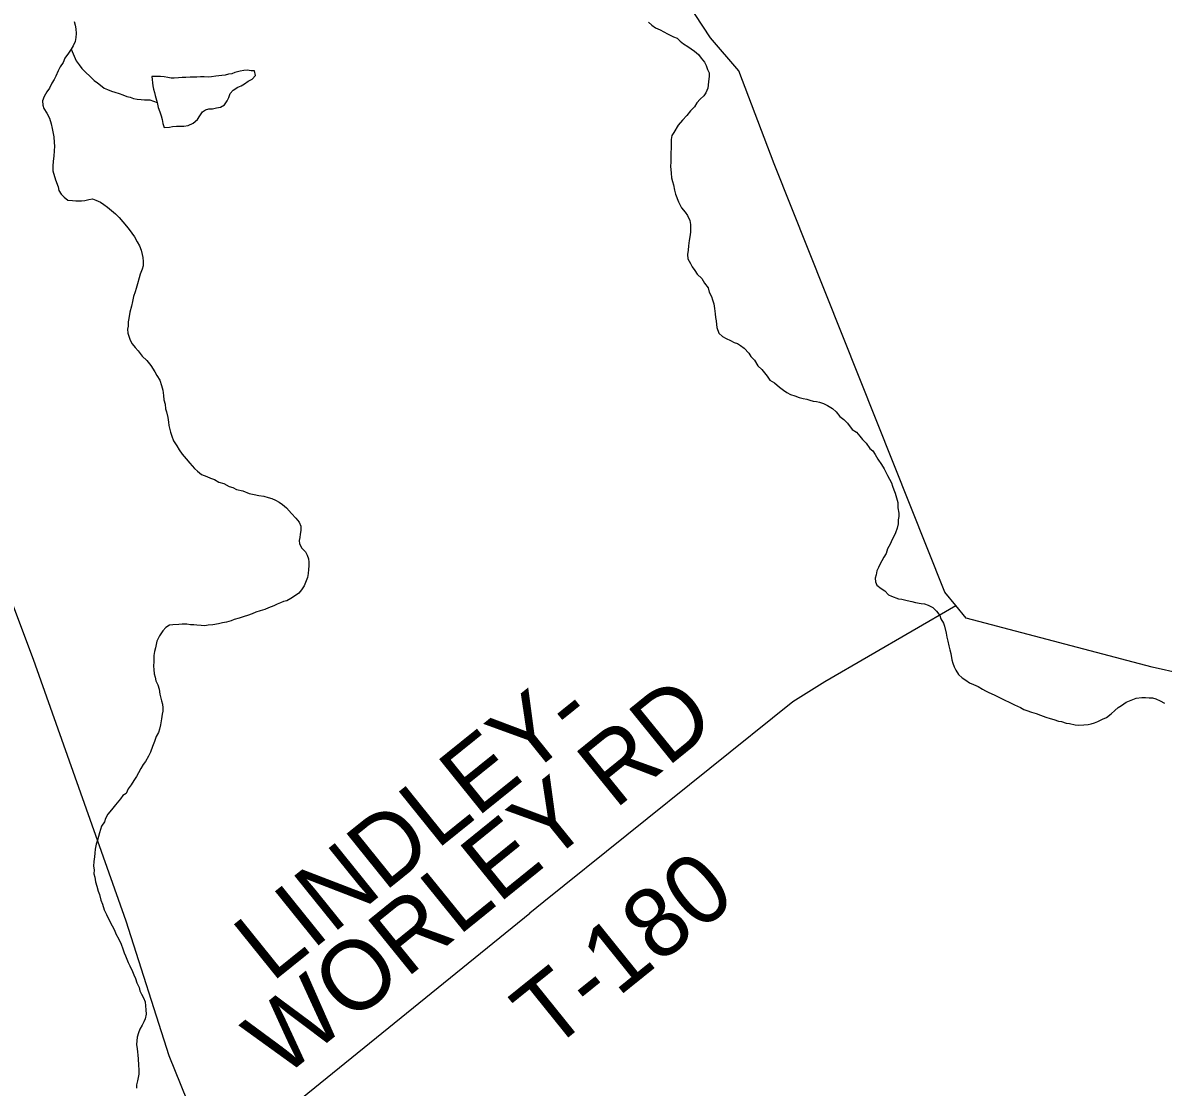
# Model space of a CAD drawing. Extents: x 1310247 to 1664935, y 284496 to 704931.
# Drawn here: x 1517006 to 1521928, y 471214 to 475811 of the extents above; entities that cross this region are included whole.
import ezdxf

# ---------------------------------------------------------------- set-up
doc = ezdxf.new("R2010")
doc.units = 0
for name, color, linetype in [('GM_X_County_Road_Text', 7, 'Continuous'), ('GM_X_County_Subdivision_Text', 7, 'Continuous'), ('GM_X_Minor_River', 7, 'Continuous'), ('GM_X_Minor_River_Text', 7, 'Continuous'), ('GM_X_Township_Subdivision', 7, 'Continuous')]:
    doc.layers.add(name, color=color, linetype=linetype)

msp = doc.modelspace()

# ---------------------------------------------------------------- linework, layer by layer
at = {"layer": 'GM_X_County_Road_Text'}
for points in [[(1512412.2, 479868.3), (1512884, 479728.6), (1513011.2, 479638.4), (1513334, 479148.4), (1513670.6, 478637.4), (1514118, 477962.6), (1514571.2, 477265.7), (1514855.2, 476804), (1515883.3, 475188.3), (1516518, 474094.8), (1516870.8, 473537.8), (1517050.2, 473063.7), (1517450.2, 471932.4), (1517635.9, 471351.9), (1517767.3, 471027)], [(1522264.5, 472942.8), (1521880.2, 473029), (1521078.1, 473239.9), (1521032.3, 473295.2), (1520985.4, 473351.7), (1520249.2, 475202.2), (1520096.8, 475603.6), (1519974.5, 475745.9), (1519874.5, 475897.9), (1519727.2, 476499.8), (1519621.9, 476700), (1519462.1, 476887), (1518873.3, 477511.8), (1518828.8, 477618.8), (1518824.3, 477628.5), (1518823.6, 477630)]]:
    msp.add_lwpolyline(points, dxfattribs=at)
at = {"layer": 'GM_X_County_Subdivision_Text'}
for points in [[(1519194.1, 471967.2), (1519255.2, 472016.7), (1520329.3, 472880.5), (1520467.2, 472966.6), (1521032.3, 473295.2)], [(1517839.6, 470867.7), (1519193.6, 471966.8), (1519194.1, 471967.2)]]:
    msp.add_lwpolyline(points, dxfattribs=at)
at = {"layer": 'GM_X_Minor_River'}
for points in [[(1517585.9, 475467.4), (1517590.2, 475445.6), (1517597.7, 475427.4), (1517603.3, 475409.2), (1517606.9, 475393.1), (1517610.5, 475376.9), (1517616.1, 475358.7), (1517638.2, 475360.2), (1517652.4, 475363.9), (1517668.5, 475365.5), (1517686.6, 475365.1), (1517700.6, 475364.7), (1517718.8, 475368.3), (1517741.1, 475377.8), (1517759.6, 475393.4), (1517770, 475409.2), (1517780.5, 475427), (1517794.8, 475434.7), (1517809, 475440.4), (1517825.1, 475440), (1517841.2, 475443.6), (1517859.4, 475447.2), (1517875.7, 475456.8), (1517888.2, 475474.6), (1517894.6, 475488.5), (1517901, 475506.4), (1517913.4, 475520.1), (1517933.9, 475533.7), (1517948.1, 475539.3), (1517962.3, 475547), (1517978.7, 475558.7), (1517995, 475568.3), (1518009.4, 475584), (1518005.9, 475604.2), (1517991.9, 475604.5), (1517973.8, 475607), (1517959.8, 475605.3), (1517943.6, 475601.7), (1517921.4, 475596.2), (1517907.2, 475590.5), (1517893, 475588.8), (1517878.9, 475585.2), (1517864.8, 475583.5), (1517838.6, 475580.1), (1517820.5, 475578.5), (1517806.4, 475576.9), (1517788.3, 475577.3), (1517772.2, 475577.7), (1517756.1, 475576.1), (1517742.1, 475576.4), (1517728, 475576.8), (1517709.9, 475575.2), (1517693.8, 475575.6), (1517677.7, 475574), (1517659.6, 475572.4), (1517645.6, 475572.7), (1517631.6, 475575.1), (1517615.5, 475577.5), (1517599.5, 475579.8), (1517562.9, 475578.7)], [(1517562.9, 475578.7), (1517566.4, 475538.5), (1517570, 475524.4), (1517573.7, 475510.2), (1517577.1, 475497)], [(1517577.1, 475497), (1517585.9, 475467.4)]]:
    msp.add_lwpolyline(points, dxfattribs=at)
at = {"layer": 'GM_X_Minor_River_Text'}
for points in [[(1517227.8, 475817.5), (1517231.4, 475801.4), (1517235, 475785.3), (1517236.5, 475765.2), (1517234.1, 475747.2), (1517231.7, 475731.2), (1517223.1, 475711.3), (1517214.8, 475697.5), (1517202.3, 475679.7), (1517187.7, 475658), (1517179.2, 475640.1), (1517166.6, 475620.4), (1517158.2, 475604.5), (1517147.6, 475580.7), (1517141.2, 475566.8)], [(1519706.6, 475814), (1519720.4, 475801.6), (1519736.1, 475789.2), (1519756, 475780.7), (1519771.9, 475772.3), (1519787.7, 475763.9), (1519813.5, 475751.2), (1519829.4, 475744.8), (1519843.2, 475732.5), (1519856.9, 475720.1), (1519876.8, 475709.6), (1519890.6, 475699.2), (1519904.4, 475688.8), (1519922.1, 475674.4), (1519933.7, 475658), (1519947.4, 475641.7), (1519955.1, 475627.4), (1519960.6, 475609.2), (1519968.3, 475595), (1519968, 475581), (1519965.4, 475557), (1519962.7, 475528.9), (1519954.1, 475509.1), (1519945.7, 475495.2), (1519929.3, 475481.6), (1519914.9, 475465.9), (1519904.4, 475448.1), (1519887.9, 475430.4), (1519871.3, 475410.7), (1519852.7, 475391.1), (1519834.1, 475369.5), (1519815.3, 475337.9), (1519806.9, 475324), (1519804.5, 475308), (1519804, 475288), (1519803.5, 475269.9), (1519803, 475249.9), (1519802.5, 475229.8), (1519802, 475209.8), (1519801.6, 475191.7), (1519804.8, 475161.5), (1519806.3, 475141.4), (1519810, 475125.3), (1519813.6, 475111.2), (1519819.1, 475089), (1519822.7, 475070.8), (1519835.9, 475038.4), (1519849.3, 475012), (1519864.9, 474993.5), (1519874.6, 474979.3), (1519884.1, 474957), (1519887.7, 474940.8), (1519887.3, 474922.8), (1519886.9, 474906.7), (1519884.4, 474886.7), (1519881.9, 474870.7), (1519879.4, 474848.7), (1519876.9, 474828.7), (1519874.4, 474810.7), (1519876, 474792.6), (1519887.5, 474772.3), (1519895.2, 474758), (1519906.8, 474741.7), (1519916.5, 474725.4), (1519936.1, 474706.9), (1519947.7, 474686.6), (1519963.2, 474666.1), (1519968.8, 474647.9), (1519978.4, 474629.6), (1519982, 474615.5), (1519987.6, 474597.3), (1519991.1, 474577.2), (1519994.6, 474555), (1519996.2, 474538.9), (1519997.9, 474524.8), (1519999.5, 474508.7), (1520001.1, 474494.7), (1520010.6, 474470.3), (1520026.3, 474455.9), (1520042.1, 474447.5), (1520060, 474439.1), (1520075.9, 474430.6), (1520089.8, 474426.3)], [(1517214.8, 475697.5), (1517235.6, 475646.8), (1517249.3, 475630.4), (1517260.9, 475614.1), (1517276.6, 475597.7), (1517296.2, 475579.1), (1517313.9, 475562.7), (1517327.7, 475552.3), (1517341.5, 475541.9), (1517357.2, 475529.5), (1517371.1, 475523.2), (1517389, 475516.7), (1517403, 475512.4), (1517420.9, 475505.9), (1517436.8, 475499.5), (1517454.7, 475493), (1517468.8, 475490.7), (1517482.7, 475484.3), (1517498.7, 475482), (1517516.7, 475479.5), (1517530.7, 475479.2), (1517544.8, 475478.8), (1517553.2, 475478.6), (1517585.9, 475467.4)], [(1517141.2, 475566.8), (1517130.8, 475551), (1517120.2, 475529.2), (1517109.7, 475513.4), (1517097.2, 475493.6), (1517090.7, 475473.7), (1517092.2, 475455.6), (1517095.9, 475441.5), (1517109.4, 475421.1), (1517120.9, 475398.8), (1517128.4, 475374.5), (1517131.9, 475354.4), (1517135.5, 475340.2), (1517139, 475318.1), (1517140.4, 475294), (1517142, 475277.9), (1517141.5, 475257.8), (1517139, 475235.8), (1517136.4, 475213.8), (1517135.9, 475191.7), (1517135.4, 475171.7), (1517146.4, 475133.3), (1517157.8, 475102.9), (1517161.4, 475086.8), (1517171, 475070.5), (1517184.7, 475058.1), (1517200.5, 475045.7), (1517220.5, 475043.2), (1517234.6, 475042.9), (1517258.7, 475042.3), (1517272.8, 475044), (1517291, 475047.5), (1517307.1, 475051.2), (1517321, 475044.8), (1517340.9, 475036.3), (1517354.7, 475025.9), (1517370.5, 475015.5), (1517388.2, 475001), (1517406, 474986.6), (1517421.6, 474970.1), (1517437.2, 474951.7), (1517452.8, 474933.3), (1517464.5, 474919), (1517476.2, 474902.6), (1517487.8, 474886.3), (1517499.4, 474865.9), (1517508.9, 474847.6), (1517516.5, 474829.4), (1517520.1, 474811.3), (1517523.8, 474797.1), (1517525.4, 474781), (1517524.9, 474761), (1517520.5, 474747), (1517511.9, 474725.2), (1517507.5, 474709.2), (1517500.8, 474683.3), (1517494.3, 474663.4), (1517489.9, 474649.5), (1517483.4, 474629.6), (1517478.8, 474607.6), (1517474.3, 474587.6), (1517467.7, 474561.7), (1517462.9, 474533.7), (1517460.6, 474519.8), (1517460.1, 474501.7), (1517457.8, 474487.7), (1517459.4, 474471.6), (1517463, 474457.5), (1517468.7, 474441.3), (1517478.3, 474425), (1517489.9, 474408.7), (1517503.7, 474394.3), (1517521.2, 474371.8), (1517540.8, 474353.3), (1517558.3, 474330.8), (1517575.7, 474304.3), (1517583.4, 474288), (1517596.9, 474267.7), (1517604.4, 474245.4), (1517609.9, 474225.2), (1517613.3, 474201), (1517614.9, 474183), (1517620.5, 474164.8), (1517622, 474144.7), (1517625.6, 474130.5), (1517631.1, 474106.3), (1517634.6, 474086.2), (1517636.2, 474072.1), (1517643.6, 474043.8), (1517649.1, 474025.6), (1517656.7, 474005.4), (1517670.2, 473985), (1517679.8, 473966.7), (1517693.4, 473948.3), (1517711, 473927.8), (1517726.6, 473909.4), (1517746.1, 473886.8), (1517759.8, 473874.5), (1517777.6, 473860), (1517799.5, 473851.5), (1517815.4, 473845)], [(1520089.8, 474426.3), (1520103.7, 474417.9), (1520119.4, 474405.5), (1520139, 474385), (1520148.7, 474370.7), (1520164.4, 474354.3), (1520177.8, 474329.9), (1520195.5, 474313.4), (1520207.2, 474299.1), (1520218.9, 474284.7), (1520230.5, 474268.4), (1520250.3, 474255.9), (1520271.9, 474237.3), (1520289.7, 474224.8), (1520303.5, 474214.5), (1520319.3, 474206.1), (1520337.3, 474199.6), (1520357.2, 474193.1), (1520373.2, 474188.7), (1520389.2, 474186.3), (1520403.1, 474182), (1520417.1, 474177.6), (1520431.1, 474175.3), (1520445.1, 474173), (1520461, 474166.5), (1520478.9, 474158.1), (1520500.6, 474145.5), (1520516.3, 474131.1), (1520531.9, 474110.7), (1520549.7, 474098.2), (1520565.3, 474081.8), (1520584.8, 474055.2), (1520604.5, 474042.7), (1520618.2, 474026.3), (1520629.9, 474012), (1520645.5, 473995.6), (1520661.1, 473973.1), (1520674.9, 473962.8), (1520684.5, 473946.5), (1520696, 473926.1), (1520711.5, 473903.7), (1520723.1, 473885.3), (1520738.5, 473856.9), (1520746.1, 473840.6), (1520755.8, 473824.4), (1520759.4, 473810.2), (1520765.1, 473794), (1520770.7, 473779.9), (1520776.3, 473759.7), (1520781.8, 473739.5), (1520783.2, 473717.3), (1520786.6, 473693.2), (1520786.3, 473679.2), (1520783.9, 473665.2), (1520783.5, 473647.1), (1520779, 473629.2), (1520772.5, 473609.3), (1520766.1, 473595.4), (1520757.7, 473579.5), (1520749.2, 473559.7), (1520738.6, 473539.8), (1520732.1, 473519.9), (1520721.7, 473504.1), (1520713.2, 473488.3), (1520706.9, 473474.4), (1520698.4, 473458.5), (1520692.1, 473444.7), (1520689.6, 473426.7), (1520685.2, 473412.7), (1520686.8, 473396.6), (1520692.5, 473382.5), (1520710.2, 473368), (1520726, 473357.6), (1520741.7, 473341.1), (1520755.6, 473334.8), (1520785.5, 473324), (1520799.5, 473321.7), (1520823.5, 473317.1), (1520843.4, 473312.6), (1520859.4, 473308.2), (1520883.4, 473303.6), (1520897.4, 473301.3), (1520913.3, 473296.9), (1520933.2, 473286.4), (1520948.8, 473269.9), (1520964.4, 473251.5), (1520968.1, 473237.4), (1520979.7, 473219), (1520983.4, 473204.9), (1520990.6, 473174.6), (1520994.3, 473158.5), (1520997.8, 473140.3), (1521003.3, 473120.1), (1521007, 473104), (1521010.6, 473087.8), (1521015.9, 473059.6), (1521019.6, 473045.5), (1521025.2, 473029.3), (1521032.9, 473015.1), (1521044.5, 472996.8), (1521060.2, 472982.3)], [(1517815.4, 473845), (1517833.3, 473838.6), (1517851.1, 473828.1), (1517873, 473821.6), (1517896.8, 473809), (1517912.8, 473804.6), (1517928.6, 473796.2), (1517954.6, 473789.5), (1517982.4, 473778.8), (1518004.4, 473774.3), (1518024.4, 473769.8), (1518046.4, 473767.2), (1518064.4, 473760.8), (1518080.3, 473756.4), (1518096.2, 473750), (1518112.1, 473741.6), (1518125.9, 473731.2), (1518143.6, 473716.8), (1518165.1, 473692.1), (1518184.7, 473671.6), (1518198.3, 473655.2), (1518205.9, 473637), (1518205.5, 473618.9), (1518203, 473603), (1518200.7, 473589), (1518198.3, 473575), (1518200, 473560.9), (1518209.6, 473542.6), (1518225.2, 473526.2), (1518232.9, 473511.9), (1518238.5, 473495.8), (1518240.2, 473481.7), (1518239.8, 473465.6), (1518239.4, 473449.6), (1518237, 473433.6), (1518234.5, 473415.6), (1518225.9, 473393.7), (1518219.6, 473379.8), (1518209.1, 473362), (1518196.7, 473348.3), (1518178.3, 473334.7), (1518161.9, 473325), (1518145.6, 473315.4), (1518131.5, 473311.7), (1518117.3, 473306), (1518103.1, 473300.4), (1518088.8, 473292.7), (1518066.5, 473285.2), (1518050.3, 473277.6), (1518030.1, 473272), (1518011.8, 473266.5), (1517995.6, 473258.8), (1517975.3, 473251.3), (1517961.1, 473247.6), (1517938.9, 473240.1), (1517918.6, 473234.6), (1517904.4, 473228.9), (1517884.2, 473223.4), (1517868, 473219.8), (1517849.9, 473216.2), (1517825.6, 473210.8), (1517805.5, 473209.2), (1517791.4, 473207.6), (1517775.3, 473208), (1517757.3, 473210.4), (1517743.3, 473210.7), (1517729.2, 473211.1), (1517713.2, 473213.5), (1517693.1, 473214), (1517679, 473212.3), (1517652.9, 473210.9), (1517638.8, 473209.2), (1517622.4, 473199.6), (1517610.1, 473185.8), (1517595.4, 473164.1), (1517584.8, 473140.3), (1517578.1, 473112.4), (1517573.7, 473096.4), (1517571.2, 473078.4), (1517570.6, 473052.4), (1517570.1, 473032.3), (1517571.7, 473018.2), (1517573.3, 473000.1), (1517576.9, 472986), (1517580.5, 472969.9), (1517588.1, 472951.6), (1517593.7, 472933.4), (1517597.2, 472911.3), (1517604.5, 472883), (1517608.2, 472868.9), (1517609.8, 472852.8), (1517609.4, 472838.7), (1517607.1, 472824.8), (1517604.5, 472804.7), (1517599.9, 472778.8), (1517595.4, 472760.8), (1517591, 472746.9), (1517580.6, 472729.1), (1517574, 472707.2), (1517565.4, 472685.3), (1517556.8, 472661.4)], [(1521060.2, 472982.3), (1521076, 472971.9), (1521091.8, 472961.5), (1521109.7, 472953), (1521129.5, 472944.5), (1521147.3, 472934.1), (1521161.2, 472925.7), (1521175.1, 472919.3), (1521198.9, 472908.8), (1521212.8, 472902.4), (1521244.6, 472885.6), (1521262.4, 472877.1), (1521286.3, 472866.5), (1521312.1, 472853.8), (1521325.9, 472845.5), (1521339.9, 472841.1), (1521359.8, 472834.6), (1521379.7, 472828.1), (1521397.7, 472821.7), (1521421.5, 472813.1), (1521439.5, 472806.6), (1521455.4, 472802.2), (1521475.4, 472795.8), (1521489.4, 472793.4), (1521509.3, 472786.9), (1521523.3, 472784.6), (1521547.3, 472780), (1521561.3, 472777.6), (1521585.4, 472779), (1521603.5, 472780.6), (1521617.7, 472784.3), (1521631.8, 472788), (1521646, 472793.6), (1521666.4, 472803.2), (1521682.6, 472810.8), (1521703.1, 472826.4), (1521719.6, 472842), (1521733.9, 472853.7), (1521748.2, 472863.4), (1521768.7, 472877), (1521782.9, 472882.6), (1521797.1, 472888.3), (1521811.3, 472894), (1521835.5, 472897.4), (1521851.5, 472897), (1521867.6, 472896.6), (1521881.6, 472896.3), (1521895.6, 472892), (1521915.5, 472883.5), (1521933.3, 472873)], [(1517556.8, 472661.4), (1517548.3, 472643.6), (1517535.7, 472621.8), (1517525.3, 472608), (1517514.8, 472590.2), (1517504.3, 472572.4), (1517495.9, 472556.5), (1517485.4, 472538.7), (1517472.9, 472521), (1517460.4, 472503.2), (1517451.9, 472483.4), (1517437.6, 472473.7), (1517427.2, 472459.9), (1517406.4, 472434.3), (1517387.8, 472412.7), (1517373.3, 472393), (1517362.8, 472375.2), (1517358.4, 472361.2), (1517345.9, 472341.5), (1517341.5, 472327.5), (1517337.1, 472313.6), (1517332.7, 472297.6), (1517328.3, 472281.7), (1517321.8, 472263.8), (1517317.3, 472241.8), (1517316.9, 472225.8), (1517314.4, 472209.8), (1517311.9, 472189.8), (1517311.4, 472169.7), (1517313, 472153.6), (1517312.6, 472135.6), (1517316.3, 472121.5), (1517319.8, 472101.3), (1517325.3, 472083.1), (1517330.8, 472060.9), (1517336.5, 472046.7), (1517341.9, 472022.5), (1517349.5, 472004.3), (1517356.9, 471980), (1517366.4, 471959.7), (1517379.8, 471933.3), (1517391.3, 471911), (1517400.9, 471892.7), (1517406.6, 471876.5), (1517420.1, 471854.1), (1517429.5, 471831.8), (1517437.1, 471811.6), (1517442.7, 471795.4), (1517448.4, 471781.2), (1517454, 471767), (1517459.7, 471752.8), (1517467.4, 471738.6), (1517478.8, 471714.2), (1517484.5, 471700), (1517492.1, 471683.8), (1517497.7, 471665.6), (1517507.2, 471645.3), (1517510.9, 471631.2), (1517518.6, 471617), (1517526.2, 471600.7), (1517533.8, 471582.5), (1517535.4, 471566.4), (1517536.9, 471548.3), (1517538.5, 471530.2), (1517534, 471510.2), (1517527.6, 471496.4), (1517521.2, 471482.5), (1517510.7, 471464.7), (1517504.3, 471448.8), (1517499.9, 471430.8), (1517497.5, 471414.8), (1517497, 471398.8), (1517498.6, 471380.7), (1517500.3, 471366.6), (1517501.9, 471352.5), (1517503.5, 471336.4), (1517504.9, 471310.3), (1517506.4, 471290.2), (1517505.9, 471270.2), (1517503.5, 471256.2), (1517501.2, 471242.2), (1517496.7, 471224.2), (1517496.3, 471210.2)]]:
    msp.add_lwpolyline(points, dxfattribs=at)

# ---------------------------------------------------------------- texts
at = {"layer": 'GM_X_Township_Subdivision'}
for s, rotation, p in [('LINDLEY-', 38.8434, (1518079.6, 471663.8)), ('WORLEY RD', 38.9869, (1518123.1, 471247.5)), ('T-180', 38.8347, (1519279.2, 471364.1))]:
    msp.add_text(s, height=300, rotation=rotation, dxfattribs=at).set_placement(p)

doc.saveas('drawing.dxf')
